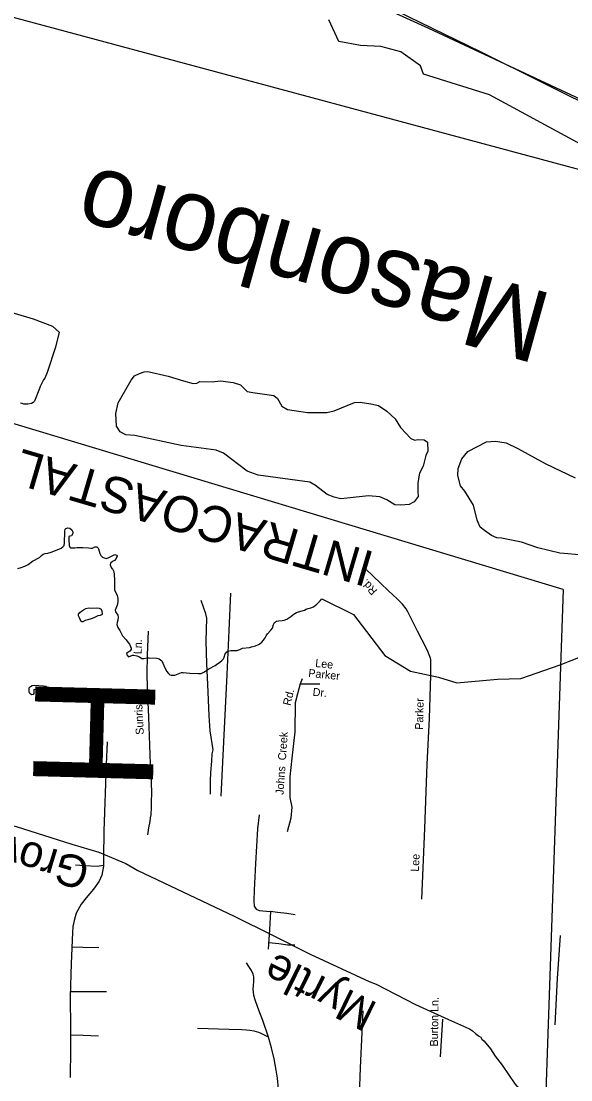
# Model space of a CAD drawing. Extents: x 2308163 to 2335412, y -96774 to 127732.
# Drawn here: x 2326126.4 to 2326217.9, y 123164.6 to 123340.9 of the extents above; entities that cross this region are included whole.
import ezdxf

# ---------------------------------------------------------------- set-up
doc = ezdxf.new("R2010")
doc.units = 0
for name, color, linetype in [('Old_Level_10', 7, 'Continuous'), ('Old_Level_11', 7, 'Continuous'), ('Old_Level_21', 7, 'Continuous'), ('Old_Level_22', 7, 'Continuous'), ('Old_Level_32', 7, 'Continuous'), ('Old_Level_35', 7, 'Continuous'), ('Old_Level_52', 7, 'Continuous'), ('Old_Level_60', 7, 'Continuous'), ('Old_Level_61', 7, 'Continuous'), ('Old_Level_63', 7, 'Continuous')]:
    doc.layers.add(name, color=color, linetype=linetype)

msp = doc.modelspace()

# ---------------------------------------------------------------- linework, layer by layer
at = {"layer": 'Old_Level_32'}
for points in [[(2326119.51, 123208.26), (2326121.41, 123207.83), (2326125.55, 123206.79), (2326134.82, 123203.84)], [(2326134.82, 123203.84), (2326139.32, 123202.5), (2326142.47, 123201.21), (2326143.79, 123200.62), (2326145.79, 123199.49), (2326161.84, 123191.86), (2326168.22, 123188.71), (2326174.49, 123185.52), (2326184.31, 123180.99), (2326185.47, 123180.51)], [(2326185.47, 123180.51), (2326192.04, 123177.16), (2326197.53, 123174.63), (2326201, 123173.1), (2326201.55, 123172.79), (2326202.02, 123172.33), (2326202.53, 123171.91), (2326202.89, 123171.7), (2326203.09, 123171.4), (2326203.39, 123171.12), (2326204.03, 123170.4), (2326204.51, 123169.77), (2326205.28, 123168.56), (2326206.46, 123167.06)], [(2326206.46, 123167.06), (2326208.59, 123163.93), (2326211.12, 123160.95), (2326213.2, 123158.1), (2326217.37, 123152.64), (2326220.52, 123148.59), (2326222.36, 123146.39), (2326224.28, 123144.02)]]:
    msp.add_lwpolyline(points, dxfattribs=at)
at = {"layer": 'Old_Level_35'}
for points in [[(2326193.1, 123194.71), (2326193.58, 123206.43), (2326194, 123217.19), (2326194.35, 123224.78), (2326194.61, 123232.01), (2326194.61, 123232.61), (2326194.61, 123233.33), (2326194.61, 123234.04), (2326194.59, 123234.53), (2326194.51, 123234.82), (2326194.32, 123235.4), (2326194.01, 123236.09), (2326193.16, 123237.82), (2326192.35, 123239.34), (2326190.75, 123242.51), (2326190.46, 123243.05), (2326189.85, 123243.79), (2326188.98, 123244.71), (2326187.55, 123246.05), (2326183.69, 123249.67)], [(2326157.91, 123212.17), (2326157.91, 123214.09), (2326157.89, 123214.86), (2326157.95, 123215.34), (2326157.96, 123215.79), (2326158.12, 123217.69), (2326158.19, 123218.91), (2326158.33, 123219.56), (2326157.84, 123222.7), (2326157.66, 123225.27), (2326157.46, 123230.43), (2326157.26, 123233.93), (2326157.19, 123237.67), (2326157.28, 123241.49), (2326157.13, 123242.19), (2326156.33, 123244.44)], [(2326159.68, 123211.82), (2326160.12, 123220.88), (2326160.68, 123232.09), (2326161.02, 123239.4), (2326161.29, 123245.65)], [(2326147.91, 123217.25), (2326147.65, 123225.02), (2326147.41, 123229.98), (2326147.34, 123232.18), (2326147.41, 123235.35), (2326147.55, 123239.29)], [(2326173.14, 123231.39), (2326172.85, 123230.53), (2326172.38, 123228.89), (2326171.97, 123227.36), (2326171.91, 123222.57), (2326171.45, 123218.16), (2326171.13, 123215.08), (2326171.12, 123211.63), (2326171.42, 123210.02), (2326171.26, 123208.17), (2326170.68, 123205.89)], [(2326172.85, 123230.53), (2326176.11, 123230.52)], [(2326140.69, 123220.91), (2326140.5, 123217.13), (2326140.11, 123206.03), (2326140.08, 123201.63), (2326140.08, 123200.18), (2326139.81, 123198.7), (2326139.36, 123197.71), (2326138.39, 123196.36), (2326137.18, 123194.89), (2326136.33, 123193.88), (2326135.54, 123192.38), (2326135.2, 123191.14), (2326134.96, 123190.12), (2326134.93, 123189.13), (2326134.68, 123183.95), (2326134.53, 123178.42), (2326134.58, 123173.21), (2326134.57, 123169.74), (2326134.53, 123164.99)], [(2326147.46, 123205.4), (2326147.65, 123206.57), (2326147.85, 123207.62), (2326147.9, 123208.23), (2326147.99, 123208.76), (2326148.06, 123209.98), (2326148.08, 123210.83), (2326148.13, 123212.4), (2326148.08, 123214.12), (2326147.91, 123217.25)], [(2326165.98, 123208.73), (2326165.73, 123206.41), (2326165.37, 123200.61), (2326165.17, 123196.18), (2326165.1, 123194.39), (2326165.18, 123193.54), (2326165.48, 123193.05), (2326166, 123192.83), (2326167.21, 123192.68), (2326167.9, 123192.65)], [(2326140.08, 123200.29), (2326139.01, 123200.14), (2326136.88, 123200.22), (2326135.39, 123200.34)], [(2326167.9, 123192.65), (2326167.74, 123189.65), (2326167.52, 123186.38)], [(2326172, 123192.09), (2326170.58, 123192.3), (2326169.05, 123192.46), (2326167.9, 123192.65)], [(2326215.31, 123173.76), (2326215.7, 123181.48), (2326216.16, 123188.62)], [(2326134.82, 123186.75), (2326136.62, 123186.72), (2326139.32, 123186.63)], [(2326167.6, 123187.46), (2326169.3, 123187.32), (2326170.77, 123187.11), (2326171.93, 123187.07)], [(2326167.58, 123171.7), (2326166.63, 123174.46), (2326165.94, 123176.22), (2326165.46, 123177.59), (2326165.27, 123178.11), (2326165.18, 123178.47), (2326165.12, 123178.67), (2326165.03, 123179.2), (2326165.01, 123179.7), (2326165.06, 123180.34), (2326165.12, 123180.99), (2326165.13, 123181.36), (2326165.09, 123181.75), (2326164.99, 123182.18), (2326164.72, 123182.79), (2326164.29, 123183.49), (2326163.9, 123184.07)], [(2326134.55, 123179.31), (2326136.37, 123179.34), (2326140.57, 123179.34)], [(2326182.54, 123157.49), (2326182.9, 123166.58), (2326183.34, 123176.08)], [(2326196.2, 123168.43), (2326196.61, 123174.73)], [(2326139.24, 123171.85), (2326136.69, 123172.01), (2326134.58, 123172.04)], [(2326167.58, 123171.7), (2326166.86, 123172.05), (2326166.33, 123172.3), (2326165.93, 123172.47), (2326165.16, 123172.7), (2326164.47, 123172.8), (2326163.91, 123172.85), (2326163.13, 123172.91), (2326161.02, 123172.96), (2326155.75, 123173.14)], [(2326169.75, 123158.81), (2326169.2, 123163.13), (2326169.04, 123164.89), (2326168.83, 123166.23), (2326168.47, 123168.11), (2326168.07, 123169.91), (2326167.58, 123171.7)]]:
    msp.add_lwpolyline(points, dxfattribs=at)
at = {"layer": 'Old_Level_52'}
msp.add_lwpolyline([(2326352.46, 123278.37), (2326344.49, 123279.39), (2326334.11, 123277.47), (2326314.41, 123278.3), (2326300.12, 123278.02), (2326291.22, 123283.57), (2326287.11, 123292.06), (2326280.06, 123298.67), (2326266.15, 123306.08), (2326194.23, 123339.67), (2326117.56, 123374.58), (2325996.97, 123429.09), (2325967.84, 123440.3), (2325941.49, 123450.31)], dxfattribs=at)
at = {"layer": 'Old_Level_60'}
for points in [[(2326127.66, 123373.96), (2326132.4, 123371.8), (2326136.14, 123367.53), (2326140.13, 123366.07), (2326143.93, 123363.85), (2326143.86, 123361.92), (2326157.43, 123357.03), (2326182.68, 123345.67), (2326202.81, 123335.85), (2326223.69, 123325.46), (2326232.34, 123320.74), (2326241.56, 123317.67)], [(2326242.1, 123310.74), (2326232.69, 123316.04), (2326219.63, 123320.35), (2326204.37, 123328.62), (2326193.35, 123332.04), (2326192.88, 123333.43), (2326189.59, 123335.76), (2326186.26, 123336.7), (2326182.89, 123336.82), (2326179.29, 123337.5), (2326177.6, 123341.14)], [(2326125.82, 123249.76), (2326126.39, 123249.91), (2326126.96, 123250.12), (2326127.55, 123250.4), (2326128.26, 123250.95), (2326129.43, 123251.59), (2326129.76, 123251.93), (2326130.04, 123252.14), (2326130.38, 123252.23), (2326130.79, 123252.28), (2326131.37, 123252.49), (2326132.62, 123252.95), (2326133, 123253.16), (2326133.31, 123253.34), (2326133.53, 123253.59), (2326133.59, 123253.96), (2326133.66, 123255.96), (2326133.72, 123256.28), (2326133.82, 123256.42), (2326134.14, 123256.52), (2326134.49, 123256.48), (2326134.78, 123256.18), (2326134.95, 123255.83), (2326134.96, 123255.58), (2326134.76, 123255.19), (2326134.45, 123255.14), (2326134.32, 123255.07), (2326134.31, 123254.51), (2326134.34, 123253.59), (2326134.48, 123253.29), (2326134.65, 123253.2), (2326135.31, 123253.21), (2326135.63, 123253.24), (2326136.11, 123253.26), (2326136.63, 123253.25), (2326137.57, 123253.21), (2326137.96, 123253.14), (2326138.27, 123253.14), (2326138.63, 123253.36), (2326138.97, 123253.35), (2326139.21, 123253.14), (2326139.27, 123253.02), (2326139.47, 123252.27), (2326139.65, 123251.92), (2326139.9, 123251.66), (2326140.21, 123251.5), (2326140.59, 123251.44), (2326140.98, 123251.56), (2326141.65, 123251.94), (2326141.97, 123252.06), (2326142.25, 123251.98), (2326142.34, 123251.78), (2326142.2, 123251.42), (2326141.88, 123251.11), (2326141.58, 123250.91), (2326141.23, 123250.64), (2326141.16, 123250.35), (2326141.3, 123250.02), (2326141.49, 123249.77), (2326141.58, 123249.71), (2326141.77, 123249.25), (2326141.87, 123248.76), (2326141.89, 123247.82), (2326141.88, 123246.71), (2326141.93, 123246.21), (2326142.34, 123245.26), (2326142.46, 123244.77), (2326142.45, 123244.19), (2326142.33, 123243.66)], [(2326160.17, 123235), (2326160.36, 123235.52), (2326160.61, 123235.85), (2326160.8, 123235.99), (2326161.26, 123236.11), (2326161.81, 123236.09), (2326162.28, 123236.11), (2326162.76, 123236.28), (2326163.21, 123236.46), (2326164.37, 123236.6), (2326164.74, 123236.68), (2326165.38, 123236.86), (2326165.88, 123237.07), (2326166.17, 123237.27), (2326166.46, 123237.51), (2326166.73, 123237.81), (2326166.98, 123238.18), (2326167.17, 123238.54), (2326167.38, 123238.85), (2326167.96, 123239.48), (2326168.22, 123239.82), (2326168.36, 123240.44), (2326168.55, 123240.75), (2326168.88, 123240.96), (2326169.21, 123241.03), (2326169.84, 123241.07), (2326170.16, 123241.14), (2326170.62, 123241.31), (2326170.95, 123241.52), (2326171.29, 123241.78), (2326171.59, 123242.04), (2326171.92, 123242.24), (2326172.24, 123242.42), (2326172.57, 123242.54), (2326173.53, 123242.84), (2326173.83, 123242.96), (2326174.16, 123243.07), (2326174.61, 123243.18), (2326175.07, 123243.36), (2326175.61, 123243.83), (2326175.9, 123244.1), (2326176.14, 123244.37), (2326176.43, 123244.71), (2326181.7, 123242.1), (2326186.9, 123235.29), (2326191.22, 123232.65), (2326195.85, 123231.66), (2326198.92, 123230.73), (2326205.68, 123231.32), (2326209.57, 123231.46), (2326216.12, 123233.73), (2326221.9, 123236.01)], [(2326139.88, 123242.08), (2326139.51, 123241.94), (2326139.16, 123241.85), (2326138.82, 123241.72), (2326138.46, 123241.54), (2326138, 123241.37), (2326137.48, 123241.21), (2326137.05, 123241.1), (2326136.61, 123240.89), (2326136.45, 123240.89), (2326136.34, 123240.96), (2326136.2, 123241.24), (2326136.09, 123241.56), (2326135.94, 123241.89), (2326135.93, 123242.17), (2326136.12, 123242.4), (2326136.43, 123242.66), (2326136.75, 123242.89), (2326137.15, 123243.09), (2326137.63, 123243.18), (2326138, 123243.17), (2326138.91, 123243.18), (2326139.36, 123243.14), (2326139.66, 123242.98), (2326139.8, 123242.69), (2326139.88, 123242.08)], [(2326142.33, 123243.66), (2326142.01, 123242.84), (2326142.06, 123242.54), (2326142.47, 123242), (2326142.51, 123241.66), (2326142.48, 123241.17), (2326142.33, 123240.76), (2326142.27, 123240.4), (2326142.46, 123239.95), (2326142.79, 123239.42), (2326143.25, 123238.56), (2326143.83, 123237.9), (2326144.15, 123237.5), (2326144.4, 123237.13), (2326144.57, 123236.78), (2326144.7, 123236.47), (2326144.71, 123236.24), (2326144.48, 123235.98), (2326144.14, 123235.79), (2326143.88, 123235.6), (2326143.94, 123235.36), (2326144.22, 123235.03), (2326144.89, 123235.3), (2326145.15, 123235.33), (2326145.65, 123235.2), (2326146.06, 123235.04), (2326146.48, 123234.78), (2326146.8, 123234.77), (2326147.3, 123234.85), (2326147.66, 123234.88), (2326148.93, 123234.8), (2326149.36, 123234.7), (2326149.78, 123234.37), (2326149.98, 123233.99), (2326150.1, 123233.62), (2326150.57, 123232.68), (2326150.92, 123232.24), (2326151.13, 123232.06), (2326151.35, 123231.98), (2326151.98, 123232), (2326153.07, 123232.41), (2326153.34, 123232.45), (2326153.91, 123232.37), (2326154.45, 123232.31), (2326155.85, 123232.27), (2326156.33, 123232.29), (2326156.77, 123232.5), (2326157.62, 123233.03), (2326158.65, 123233.58), (2326158.92, 123233.76), (2326159.44, 123234.15), (2326159.76, 123234.43), (2326160.04, 123234.71), (2326160.17, 123235)], [(2326134.67, 123228.64), (2326134.51, 123228.33), (2326134.37, 123228.19), (2326134.05, 123228.21), (2326132.89, 123228.46), (2326132.54, 123228.5), (2326132.2, 123228.51), (2326131.88, 123228.55), (2326131.53, 123228.69), (2326131.25, 123228.85), (2326130.81, 123229.29), (2326130.57, 123229.38), (2326128.86, 123229.57), (2326128.54, 123229.58), (2326128.45, 123229.52), (2326128.45, 123228.95), (2326128.34, 123228.79), (2326128.09, 123228.73), (2326127.79, 123228.93), (2326127.69, 123229.18), (2326127.69, 123229.53), (2326127.72, 123229.86), (2326127.92, 123230.12), (2326128.19, 123230.29), (2326128.52, 123230.31), (2326130.09, 123230.23), (2326130.47, 123230.14), (2326131.07, 123229.74), (2326131.46, 123229.61), (2326132.13, 123229.58), (2326133.46, 123229.7), (2326133.85, 123229.69), (2326134.41, 123229.57), (2326134.6, 123229.29), (2326134.68, 123228.96), (2326134.67, 123228.64)]]:
    msp.add_lwpolyline(points, dxfattribs=at)
at = {"layer": 'Old_Level_61'}
for points in [[(2326122.53, 123293.03), (2326128.38, 123291.3), (2326131.58, 123290.08), (2326132.7, 123289.1), (2326132.06, 123286.59), (2326130.7, 123282.38)], [(2326130.7, 123282.38), (2326130.28, 123281.45), (2326130.09, 123281.19), (2326129.54, 123280.05), (2326129.42, 123279.72), (2326128.6, 123277.6), (2326128.37, 123277.39), (2326128.08, 123277.25)], [(2326194.08, 123269.3), (2326193.75, 123268.55), (2326193.3, 123266.77), (2326192.71, 123265.61), (2326192.43, 123264.04), (2326192.42, 123262.63), (2326192.45, 123261.74), (2326191.8, 123260.88), (2326190.98, 123260.39), (2326189.58, 123260.27), (2326188.59, 123260.35), (2326187.28, 123261.18), (2326186.08, 123261.71), (2326184.19, 123261.84), (2326180.65, 123261.45), (2326179.57, 123261.36), (2326178.49, 123261.62), (2326177.34, 123262.07), (2326175.36, 123263.6), (2326174.43, 123264.1), (2326165.83, 123265.32), (2326164, 123265.98), (2326160.06, 123268.95), (2326158.81, 123269.48), (2326153.01, 123270.23), (2326145.29, 123271.88), (2326143.79, 123272.03), (2326142.85, 123272.51), (2326142.23, 123273.48), (2326142.12, 123275.57), (2326142.5, 123277.36), (2326144.7, 123281.11), (2326145.25, 123281.83), (2326146.05, 123282.21), (2326146.83, 123282.49), (2326147.48, 123282.58), (2326150.82, 123281.77), (2326153.38, 123280.99), (2326154.98, 123280.56), (2326155.64, 123280.6), (2326156.1, 123280.9), (2326158.17, 123280.83), (2326159.58, 123280.98), (2326161.66, 123280.71), (2326162.9, 123280.35), (2326163.99, 123279.23), (2326164.97, 123279.07), (2326168.45, 123278.54), (2326169.07, 123278.04), (2326169.8, 123276.81), (2326170.7, 123276.25), (2326174.05, 123275.72), (2326177.29, 123275.75), (2326178.47, 123276.01), (2326181.88, 123277.38), (2326182.81, 123277.44), (2326184.59, 123277.15), (2326185.89, 123276.89), (2326187.27, 123275.96), (2326188.67, 123274.7), (2326189.51, 123273.25), (2326191.26, 123271.4), (2326191.94, 123271.1), (2326192.42, 123271.22), (2326193.45, 123271.19), (2326194.02, 123270.77), (2326194.08, 123269.3)], [(2326128.08, 123277.25), (2326127.45, 123277.11), (2326127.14, 123277.11), (2326126.83, 123277.13), (2326126.54, 123277.24), (2326126.24, 123277.31)], [(2326219.99, 123251.96), (2326216.07, 123252.29), (2326212.39, 123253.2), (2326209.7, 123254.16), (2326206.33, 123254.78), (2326205.56, 123254.87), (2326204.69, 123255.26), (2326203.52, 123256.08), (2326202.82, 123256.62), (2326202.32, 123257.82), (2326201.7, 123260.28), (2326200.23, 123262.61), (2326199.54, 123263.53), (2326199.08, 123265.26), (2326199.11, 123266.4), (2326199.76, 123268.03), (2326200.77, 123269.21), (2326203.85, 123270.87), (2326205.36, 123270.98), (2326207.12, 123270.7), (2326209.08, 123269.75), (2326213.65, 123267.24), (2326218.62, 123264.86)]]:
    msp.add_lwpolyline(points, dxfattribs=at)
at = {"layer": 'Old_Level_63'}
msp.add_line((2326216.61, 123246.24), (2326051.48, 123296.05), dxfattribs=at)
for points in [[(2326475.8, 123239.36), (2326422.14, 123261.61), (2325934.09, 123392.92)], [(2326216.61, 123246.24), (2326207.41, 122979.25), (2326040.74, 122984.51), (2326051.48, 123296.05)]]:
    msp.add_lwpolyline(points, dxfattribs=at)

# ---------------------------------------------------------------- texts
at = {"layer": 'Old_Level_10'}
for s, height, rotation, p in [('Rd.', 1.333, 132.9634, (2326185.76, 123246.09)), ('Ln.', 1.333, 88.0624, (2326146.42, 123235.47)), ('Lee', 1.333, 354.2925, (2326175.29, 123233.36)), ('Parker', 1.333, 354.2925, (2326174.14, 123231.7)), ('Rd.', 1.333, 76.1913, (2326171.21, 123226.83)), ('Dr.', 1.333, 354.2925, (2326174.86, 123228.57)), ('Sunrise', 1.333, 92.8193, (2326146.79, 123222.1)), ('Parker', 1.333, 88.7193, (2326193.28, 123222.89)), ('Johns  Creek ', 1.3328, 86.0484, (2326170.05, 123212.04)), ('Lee', 1.333, 86.8925, (2326192.57, 123199.24)), ('Burton Ln.', 1.333, 89.2977, (2326195.77, 123170.15))]:
    msp.add_text(s, height=height, rotation=rotation, dxfattribs=at).set_placement(p)
at = {"layer": 'Old_Level_11'}
for s, rotation, p in [('Grove', 163.1736, (2326138.15, 123201.18)), ('Myrtle', 153.5957, (2326185.94, 123177.27))]:
    msp.add_text(s, height=5.331, rotation=rotation, dxfattribs=at).set_placement(p)
at = {"layer": 'Old_Level_21'}
for s, height, rotation, p in [('Masonboro         Sound', 12, 164.4586, (2326215.14, 123295.36)), ('INTRACOASTAL', 5.9978, 163.6158, (2326185.46, 123252.39))]:
    msp.add_text(s, height=height, rotation=rotation, dxfattribs=at).set_placement(p)
at = {"layer": 'Old_Level_22'}
msp.add_text('H', height=19.99, rotation=268.4797, dxfattribs=at).set_placement((2326128.8, 123232.3))

doc.saveas('drawing.dxf')
